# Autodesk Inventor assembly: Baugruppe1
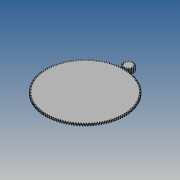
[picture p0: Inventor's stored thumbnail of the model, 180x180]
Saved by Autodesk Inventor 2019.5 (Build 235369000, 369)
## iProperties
Created: 2021-12
Part Number: Baugruppe1
Material: Generisch
Document SubType Name: Assembly
Mass: 38.8156 g
Surface Area: 72.4414 cm^2
Volume: 4.94467 cm^3
Density: 7.85 g/cm^3
Masse: 0,04 kg
Fläche: 7280,5 mm^2
Volumen: 4966,98 mm^3
Abmasse: 65 mm x 72,78 mm x 4 mm
Mass: 0.04
Keywords: =<Zeichnungsnummer><Korrektur>
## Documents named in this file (2)
- C:\Users\Walter\Downloads\Zahn\Baugruppe1.iam
- C:\Users\Walter\Downloads\Zahn\Baugruppe1\Konstruktions-Assistent\Stirnräder1.iam
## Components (1 placed, 1 different names)
1. Stirnräder:1 [sub-assembly]
